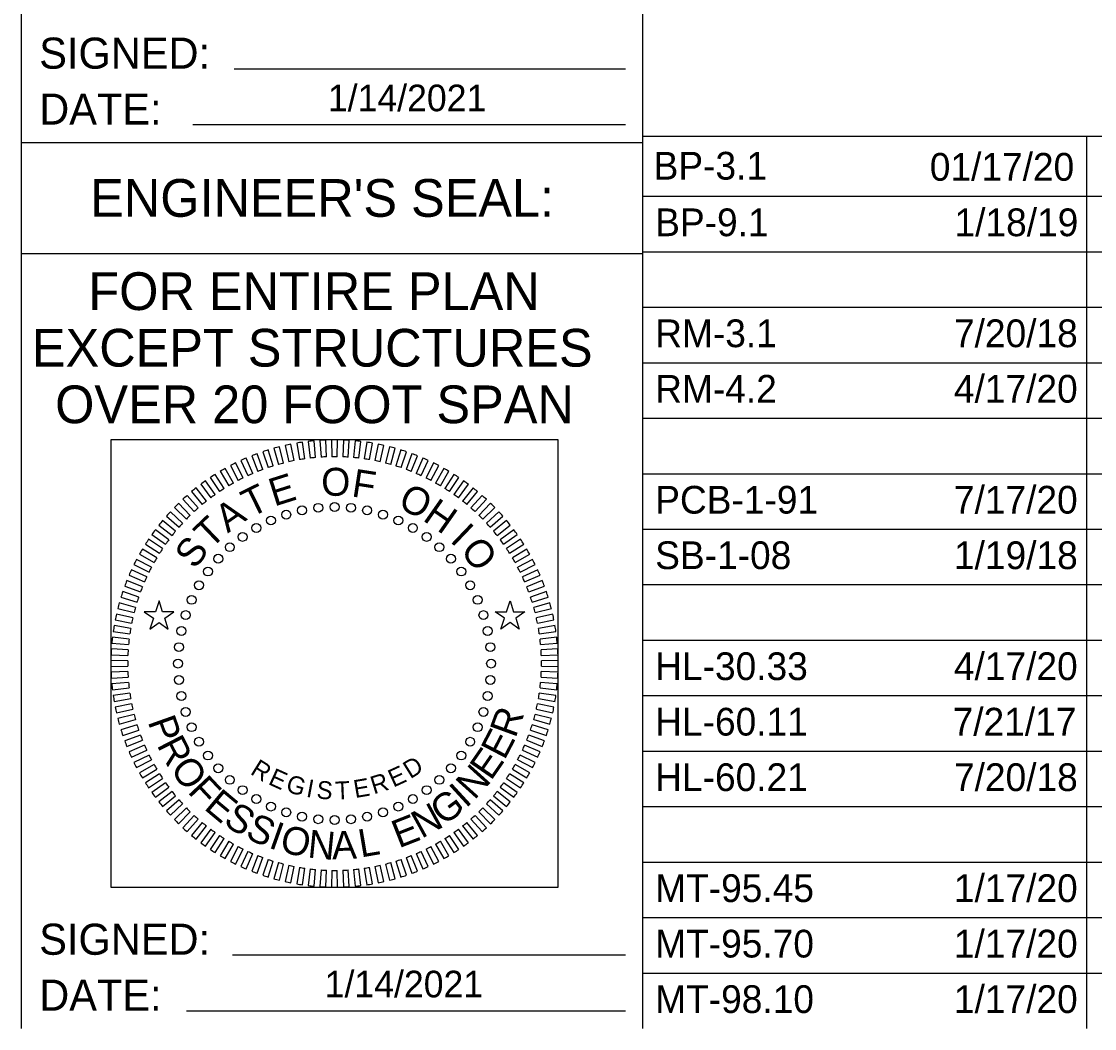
# Model space of a CAD drawing. Extents: x 2080852 to 2433556, y 1080825 to 1306626.
# Drawn here: x 2166916 to 2217967, y 1086105 to 1134021 of the extents above; entities that cross this region are included whole.
import ezdxf

# ---------------------------------------------------------------- set-up
doc = ezdxf.new("R2010")
doc.units = 0
for name, color, linetype in [('Default', 7, 'Continuous'), ('PM_P_Lane_Line', 7, 'Continuous'), ('SC_Scratch1', 7, 'Continuous')]:
    doc.layers.add(name, color=color, linetype=linetype)

msp = doc.modelspace()

# ---------------------------------------------------------------- linework, layer by layer
at = {"layer": 'PM_P_Lane_Line'}
for p, q in [((2166916, 1086105), (2166916, 1167965)), ((2196484, 1086105), (2196484, 1167965)), ((2177035, 1131774), (2195653, 1131774)), ((2175069, 1129114), (2195653, 1129114)), ((2166916, 1128264), (2196484, 1128264)), ((2196484, 1128566), (2338516, 1128566)), ((2217604, 1086105), (2217604, 1128566)), ((2196484, 1125705), (2338516, 1125705)), ((2166916, 1122984), (2196484, 1122984)), ((2196484, 1123065), (2338516, 1123065)), ((2196484, 1120425), (2338516, 1120425)), ((2196484, 1117785), (2338516, 1117785)), ((2196484, 1115145), (2338516, 1115145)), ((2180010, 1113959), (2180146, 1113173)), ((2180400, 1113213), (2180286, 1114003)), ((2180562, 1114039), (2180656, 1113246)), ((2180912, 1113273), (2180839, 1114068)), ((2181116, 1114090), (2181169, 1113294)), ((2181426, 1113307), (2181395, 1114104)), ((2181673, 1114112), (2181684, 1113314)), ((2181941, 1113314), (2181952, 1114112)), ((2182230, 1114104), (2182199, 1113307)), ((2182456, 1113294), (2182508, 1114090)), ((2182786, 1114068), (2182713, 1113273)), ((2182969, 1113246), (2183063, 1114039)), ((2183339, 1114003), (2183225, 1113213)), ((2183479, 1113173), (2183614, 1113959)), ((2178406, 1112706), (2178130, 1113455)), ((2178392, 1113548), (2178649, 1112792)), ((2178894, 1112872), (2178657, 1113634)), ((2178924, 1113713), (2179141, 1112945)), ((2179390, 1113012), (2179193, 1113785)), ((2179464, 1113850), (2179640, 1113072)), ((2179892, 1113126), (2179737, 1113908)), ((2183888, 1113908), (2183732, 1113126)), ((2183985, 1113072), (2184161, 1113850)), ((2184431, 1113785), (2184235, 1113012)), ((2184484, 1112945), (2184701, 1113713)), ((2184968, 1113634), (2184731, 1112872)), ((2184976, 1112792), (2185233, 1113548)), ((2185495, 1113455), (2185219, 1112706)), ((2177459, 1112300), (2177106, 1113015)), ((2177358, 1113135), (2177692, 1112411)), ((2177927, 1112515), (2177612, 1113249)), ((2177870, 1113355), (2178165, 1112614)), ((2185459, 1112614), (2185755, 1113355)), ((2186013, 1113249), (2185698, 1112515)), ((2185933, 1112411), (2186267, 1113135)), ((2186518, 1113015), (2186165, 1112300)), ((2176560, 1111796), (2176135, 1112471)), ((2176372, 1112617), (2176780, 1111931)), ((2177003, 1112060), (2176613, 1112756)), ((2176858, 1112889), (2177230, 1112183)), ((2186395, 1112183), (2186767, 1112889)), ((2187011, 1112756), (2186621, 1112060)), ((2186845, 1111931), (2187253, 1112617)), ((2187490, 1112471), (2187064, 1111796)), ((2196484, 1112505), (2338516, 1112505)), ((2175446, 1111998), (2175924, 1111359)), ((2176132, 1111510), (2175671, 1112162)), ((2175901, 1112319), (2176344, 1111656)), ((2187280, 1111656), (2187724, 1112319)), ((2187953, 1112162), (2187493, 1111510)), ((2187701, 1111359), (2188179, 1111998)), ((2175323, 1110872), (2174797, 1111472)), ((2175009, 1111653), (2175519, 1111040)), ((2175719, 1111202), (2175225, 1111828)), ((2188400, 1111828), (2187906, 1111202)), ((2188106, 1111040), (2188616, 1111653)), ((2188828, 1111472), (2188302, 1110872)), ((2174191, 1110897), (2174762, 1110340)), ((2174945, 1110522), (2174388, 1111094)), ((2174590, 1111286), (2175131, 1110700)), ((2188493, 1110700), (2189035, 1111286)), ((2189237, 1111094), (2188680, 1110522)), ((2188862, 1110340), (2189434, 1110897)), ((2173813, 1110488), (2174413, 1109962)), ((2174585, 1110153), (2173999, 1110695)), ((2189626, 1110695), (2189040, 1110153)), ((2189212, 1109962), (2189812, 1110488)), ((2173456, 1110060), (2174083, 1109566)), ((2174245, 1109766), (2173632, 1110276)), ((2189993, 1110276), (2189379, 1109766)), ((2189542, 1109566), (2190168, 1110060)), ((2196484, 1109865), (2338516, 1109865)), ((2173629, 1108941), (2172965, 1109384)), ((2173123, 1109613), (2173775, 1109153)), ((2173926, 1109361), (2173287, 1109839)), ((2190338, 1109839), (2189698, 1109361)), ((2189850, 1109153), (2190502, 1109613)), ((2190659, 1109384), (2189996, 1108941)), ((2173354, 1108505), (2172668, 1108913)), ((2172814, 1109150), (2173489, 1108724)), ((2190136, 1108724), (2190811, 1109150)), ((2190957, 1108913), (2190271, 1108505)), ((2173102, 1108055), (2172396, 1108427)), ((2172529, 1108672), (2173225, 1108282)), ((2190400, 1108282), (2191096, 1108672)), ((2191229, 1108427), (2190523, 1108055)), ((2172874, 1107593), (2172150, 1107927)), ((2172269, 1108179), (2172985, 1107826)), ((2190640, 1107826), (2191355, 1108179)), ((2191475, 1107927), (2190750, 1107593)), ((2172671, 1107120), (2171930, 1107415)), ((2172036, 1107673), (2172769, 1107358)), ((2190855, 1107358), (2191588, 1107673)), ((2191695, 1107415), (2190954, 1107120)), ((2172493, 1106636), (2171737, 1106893)), ((2171830, 1107155), (2172579, 1106879)), ((2191046, 1106879), (2191795, 1107155)), ((2191888, 1106893), (2191132, 1106636)), ((2196484, 1107225), (2338516, 1107225)), ((2172340, 1106144), (2171572, 1106361)), ((2171651, 1106628), (2172413, 1106391)), ((2191212, 1106391), (2191974, 1106628)), ((2192053, 1106361), (2191285, 1106144)), ((2172213, 1105645), (2171435, 1105821)), ((2171500, 1106092), (2172273, 1105895)), ((2191352, 1105895), (2192125, 1106092)), ((2192190, 1105821), (2191412, 1105645)), ((2172112, 1105139), (2171326, 1105274)), ((2171377, 1105548), (2172159, 1105393)), ((2191465, 1105393), (2192248, 1105548)), ((2192299, 1105274), (2191512, 1105139)), ((2171282, 1104999), (2172072, 1104885)), ((2191553, 1104885), (2192342, 1104999)), ((2171217, 1104446), (2172011, 1104373)), ((2172038, 1104629), (2171246, 1104723)), ((2192379, 1104723), (2191586, 1104629)), ((2191613, 1104373), (2192408, 1104446)), ((2196484, 1104585), (2338516, 1104585)), ((2171180, 1103890), (2171978, 1103859)), ((2171991, 1104116), (2171195, 1104168)), ((2192430, 1104168), (2191633, 1104116)), ((2191647, 1103859), (2192444, 1103890)), ((2171971, 1103601), (2171173, 1103612)), ((2171173, 1103333), (2171971, 1103344)), ((2192452, 1103612), (2191654, 1103601)), ((2191654, 1103344), (2192452, 1103333)), ((2171978, 1103086), (2171180, 1103055)), ((2171195, 1102777), (2171991, 1102829)), ((2191633, 1102829), (2192430, 1102777)), ((2192444, 1103055), (2191647, 1103086)), ((2172011, 1102572), (2171217, 1102499)), ((2171246, 1102222), (2172038, 1102316)), ((2191586, 1102316), (2192379, 1102222)), ((2192408, 1102499), (2191613, 1102572)), ((2172072, 1102060), (2171282, 1101946)), ((2171326, 1101671), (2172112, 1101806)), ((2191512, 1101806), (2192299, 1101671)), ((2192342, 1101946), (2191553, 1102060)), ((2196484, 1101945), (2338516, 1101945)), ((2172159, 1101552), (2171377, 1101397)), ((2171435, 1101124), (2172213, 1101300)), ((2191412, 1101300), (2192190, 1101124)), ((2192248, 1101397), (2191465, 1101552)), ((2172273, 1101050), (2171500, 1100853)), ((2171572, 1100584), (2172340, 1100801)), ((2191285, 1100801), (2192053, 1100584)), ((2192125, 1100853), (2191352, 1101050)), ((2172413, 1100554), (2171651, 1100317)), ((2171737, 1100052), (2172493, 1100309)), ((2191132, 1100309), (2191888, 1100052)), ((2191974, 1100317), (2191212, 1100554)), ((2172579, 1100066), (2171830, 1099790)), ((2171930, 1099530), (2172671, 1099825)), ((2190954, 1099825), (2191695, 1099530)), ((2191795, 1099790), (2191046, 1100066)), ((2172769, 1099587), (2172036, 1099272)), ((2172150, 1099018), (2172874, 1099352)), ((2190750, 1099352), (2191475, 1099018)), ((2191588, 1099272), (2190855, 1099587)), ((2196484, 1099305), (2338516, 1099305)), ((2172985, 1099119), (2172269, 1098766)), ((2172396, 1098518), (2173102, 1098890)), ((2173225, 1098663), (2172529, 1098273)), ((2191096, 1098273), (2190400, 1098663)), ((2190523, 1098890), (2191229, 1098518)), ((2191355, 1098766), (2190640, 1099119)), ((2172668, 1098032), (2173354, 1098440)), ((2173489, 1098221), (2172814, 1097795)), ((2190811, 1097795), (2190136, 1098221)), ((2190271, 1098440), (2190957, 1098032)), ((2172965, 1097561), (2173629, 1098004)), ((2173775, 1097792), (2173123, 1097332)), ((2190502, 1097332), (2189850, 1097792)), ((2189996, 1098004), (2190659, 1097561)), ((2173287, 1097106), (2173926, 1097584)), ((2174083, 1097379), (2173456, 1096885)), ((2173632, 1096669), (2174245, 1097179)), ((2189379, 1097179), (2189993, 1096669)), ((2190168, 1096885), (2189542, 1097379)), ((2189698, 1097584), (2190338, 1097106)), ((2174413, 1096983), (2173813, 1096457)), ((2173999, 1096250), (2174585, 1096792)), ((2174762, 1096605), (2174191, 1096048)), ((2189434, 1096048), (2188862, 1096605)), ((2189040, 1096792), (2189626, 1096250)), ((2189812, 1096457), (2189212, 1096983)), ((2196484, 1096665), (2338516, 1096665)), ((2174388, 1095851), (2174945, 1096423)), ((2175131, 1096245), (2174590, 1095659)), ((2174797, 1095473), (2175323, 1096073)), ((2188302, 1096073), (2188828, 1095473)), ((2189035, 1095659), (2188493, 1096245)), ((2188680, 1096423), (2189237, 1095851)), ((2175519, 1095905), (2175009, 1095292)), ((2175225, 1095117), (2175719, 1095743)), ((2175924, 1095586), (2175446, 1094947)), ((2188179, 1094947), (2187701, 1095586)), ((2187906, 1095743), (2188400, 1095117)), ((2188616, 1095292), (2188106, 1095905)), ((2175671, 1094783), (2176132, 1095435)), ((2176344, 1095289), (2175901, 1094625)), ((2176135, 1094474), (2176560, 1095149)), ((2187064, 1095149), (2187490, 1094474)), ((2187724, 1094625), (2187280, 1095289)), ((2187493, 1095435), (2187953, 1094783)), ((2176780, 1095014), (2176372, 1094328)), ((2176613, 1094189), (2177003, 1094885)), ((2177230, 1094762), (2176858, 1094056)), ((2177106, 1093930), (2177459, 1094645)), ((2177692, 1094534), (2177358, 1093810)), ((2186267, 1093810), (2185933, 1094534)), ((2186165, 1094645), (2186518, 1093930)), ((2186767, 1094056), (2186395, 1094762)), ((2186621, 1094885), (2187011, 1094189)), ((2187253, 1094328), (2186845, 1095014)), ((2177612, 1093696), (2177927, 1094430)), ((2178165, 1094331), (2177870, 1093590)), ((2178130, 1093490), (2178406, 1094239)), ((2178649, 1094153), (2178392, 1093397)), ((2178657, 1093311), (2178894, 1094073)), ((2184731, 1094073), (2184968, 1093311)), ((2185233, 1093397), (2184976, 1094153)), ((2185219, 1094239), (2185495, 1093490)), ((2185755, 1093590), (2185459, 1094331)), ((2185698, 1094430), (2186013, 1093696)), ((2196484, 1094025), (2338516, 1094025)), ((2179141, 1094000), (2178924, 1093232)), ((2179193, 1093160), (2179390, 1093933)), ((2179640, 1093873), (2179464, 1093095)), ((2179737, 1093037), (2179892, 1093819)), ((2180146, 1093772), (2180010, 1092986)), ((2180286, 1092942), (2180400, 1093732)), ((2180656, 1093699), (2180562, 1092906)), ((2180839, 1092877), (2180912, 1093672)), ((2181169, 1093651), (2181116, 1092855)), ((2181395, 1092840), (2181426, 1093638)), ((2181684, 1093631), (2181673, 1092833)), ((2181952, 1092833), (2181941, 1093631)), ((2182199, 1093638), (2182230, 1092840)), ((2182508, 1092855), (2182456, 1093651)), ((2182713, 1093672), (2182786, 1092877)), ((2183063, 1092906), (2182969, 1093699)), ((2183225, 1093732), (2183339, 1092942)), ((2183614, 1092986), (2183479, 1093772)), ((2183732, 1093819), (2183888, 1093037)), ((2184161, 1093095), (2183985, 1093873)), ((2184235, 1093933), (2184431, 1093160)), ((2184701, 1093232), (2184484, 1094000)), ((2196484, 1091385), (2338516, 1091385)), ((2176960, 1089615), (2195653, 1089615)), ((2196484, 1088745), (2338516, 1088745)), ((2174767, 1086955), (2195653, 1086955))]:
    msp.add_line(p, q, dxfattribs=at)
for points in [[(2173897, 1105112), (2173731, 1105623), (2174165, 1105939), (2173628, 1105939), (2173462, 1106450), (2173296, 1105939), (2172758, 1105939), (2173193, 1105623), (2173027, 1105112), (2173462, 1105427), (2173897, 1105112)], [(2189728, 1105112), (2189894, 1105623), (2189459, 1105939), (2189997, 1105939), (2190163, 1106450), (2190329, 1105939), (2190867, 1105939), (2190432, 1105623), (2190598, 1105112), (2190163, 1105427), (2189728, 1105112)]]:
    msp.add_lwpolyline(points, dxfattribs=at)
for centre in [(2180264, 1110758), (2181034, 1110880), (2181812, 1110921), (2182591, 1110880), (2183361, 1110758), (2178783, 1110277), (2179511, 1110556), (2184114, 1110556), (2184842, 1110277), (2178088, 1109923), (2185536, 1109923), (2177434, 1109498), (2186190, 1109498), (2176829, 1109008), (2186796, 1109008), (2176277, 1108456), (2187347, 1108456), (2175787, 1107850), (2187838, 1107850), (2175362, 1107197), (2188263, 1107197), (2175008, 1106502), (2188617, 1106502), (2174729, 1105774), (2188896, 1105774), (2174527, 1105021), (2189098, 1105021), (2174405, 1104251), (2189220, 1104251), (2174364, 1103472), (2189260, 1103472), (2174405, 1102694), (2189220, 1102694), (2174527, 1101924), (2189098, 1101924), (2174729, 1101171), (2188896, 1101171), (2175008, 1100443), (2188617, 1100443), (2175362, 1099748), (2188263, 1099748), (2175787, 1099095), (2187838, 1099095), (2176277, 1098489), (2187347, 1098489), (2176829, 1097937), (2186796, 1097937), (2177434, 1097447), (2186190, 1097447), (2178088, 1097022), (2185536, 1097022), (2178783, 1096668), (2179511, 1096389), (2184114, 1096389), (2184842, 1096668), (2180264, 1096187), (2181034, 1096065), (2181812, 1096024), (2182591, 1096065), (2183361, 1096187)]:
    msp.add_circle(centre, 213, dxfattribs=at)
for radius, start, end in [(10640, 98.25, 99.75), (10640, 95.25, 96.75), (10640, 92.25, 93.75), (10640, 89.25, 90.75), (10640, 86.25, 87.75), (10640, 83.25, 84.75), (10640, 80.25, 81.75), (10640, 110.25, 111.75), (10640, 107.25, 108.75), (10640, 104.25, 105.75), (10640, 101.25, 102.75), (10640, 77.25, 78.75), (10640, 74.25, 75.75), (10640, 71.25, 72.75), (10640, 68.25, 69.75), (10640, 116.25, 117.75), (10640, 113.25, 114.75), (9842, 104.25, 105.75), (9842, 101.25, 102.75), (9842, 98.25, 99.75), (9842, 95.25, 96.75), (9842, 92.25, 93.75), (9842, 89.25, 90.75), (9842, 86.25, 87.75), (9842, 83.25, 84.75), (9842, 80.25, 81.75), (9842, 77.25, 78.75), (9842, 74.25, 75.75), (10640, 65.25, 66.75), (10640, 62.25, 63.75), (10640, 122.25, 123.75), (10640, 119.25, 120.75), (9842, 113.25, 114.75), (9842, 110.25, 111.75), (9842, 107.25, 108.75), (9842, 71.25, 72.75), (9842, 68.25, 69.75), (9842, 65.25, 66.75), (10640, 59.25, 60.75), (10640, 56.25, 57.75), (10640, 125.25, 126.75), (9842, 119.25, 120.75), (9842, 116.25, 117.75), (9842, 62.25, 63.75), (9842, 59.25, 60.75), (10640, 53.25, 54.75), (10640, 131.25, 132.75), (10640, 128.25, 129.75), (9842, 125.25, 126.75), (9842, 122.25, 123.75), (9842, 56.25, 57.75), (9842, 53.25, 54.75), (10640, 50.25, 51.75), (10640, 47.25, 48.75), (10640, 134.25, 135.75), (9842, 131.25, 132.75), (9842, 128.25, 129.75), (9842, 50.25, 51.75), (9842, 47.25, 48.75), (10640, 44.25, 45.75), (10640, 137.25, 138.75), (9842, 134.25, 135.75), (9842, 44.25, 45.75), (10640, 41.25, 42.75), (10640, 140.25, 141.75), (9842, 137.25, 138.75), (9842, 41.25, 42.75), (10640, 38.25, 39.75), (10640, 146.25, 147.75), (10640, 143.25, 144.75), (9842, 143.25, 144.75), (9842, 140.25, 141.75), (9842, 38.25, 39.75), (9842, 35.25, 36.75), (10640, 35.25, 36.75), (10640, 32.25, 33.75), (10640, 149.25, 150.75), (9842, 146.25, 147.75), (9842, 32.25, 33.75), (10640, 29.25, 30.75), (10640, 152.25, 153.75), (9842, 149.25, 150.75), (9842, 29.25, 30.75), (10640, 26.25, 27.75), (10640, 155.25, 156.75), (9842, 152.25, 153.75), (9842, 26.25, 27.75), (10640, 23.25, 24.75), (10640, 158.25, 159.75), (9842, 155.25, 156.75), (9842, 23.25, 24.75), (10640, 20.25, 21.75), (10640, 161.25, 162.75), (9842, 158.25, 159.75), (9842, 20.25, 21.75), (10640, 17.25, 18.75), (10640, 164.25, 165.75), (9842, 161.25, 162.75), (9842, 17.25, 18.75), (10640, 14.25, 15.75), (10640, 167.25, 168.75), (9842, 164.25, 165.75), (9842, 14.25, 15.75), (10640, 11.25, 12.75), (10640, 170.25, 171.75), (9842, 167.25, 168.75), (9842, 11.25, 12.75), (10640, 8.25, 9.75), (9842, 170.25, 171.75), (9842, 8.25, 9.75), (10640, 173.25, 174.75), (9842, 173.25, 174.75), (9842, 5.25, 6.75), (10640, 5.25, 6.75), (10640, 176.25, 177.75), (9842, 176.25, 177.75), (9842, 2.25, 3.75), (10640, 2.25, 3.75), (10640, 179.25, 180.75), (9842, 179.25, 180.75), (9842, 359.25, 0.75), (10640, 359.25, 0.75), (10640, 182.25, 183.75), (9842, 182.25, 183.75), (9842, 356.25, 357.75), (10640, 356.25, 357.75), (10640, 185.25, 186.75), (9842, 185.25, 186.75), (9842, 353.25, 354.75), (10640, 353.25, 354.75), (10640, 188.25, 189.75), (9842, 188.25, 189.75), (9842, 350.25, 351.75), (10640, 350.25, 351.75), (10640, 191.25, 192.75), (9842, 191.25, 192.75), (9842, 347.25, 348.75), (10640, 347.25, 348.75), (10640, 194.25, 195.75), (9842, 194.25, 195.75), (9842, 344.25, 345.75), (10640, 344.25, 345.75), (10640, 197.25, 198.75), (9842, 197.25, 198.75), (9842, 341.25, 342.75), (10640, 341.25, 342.75), (10640, 200.25, 201.75), (9842, 200.25, 201.75), (9842, 338.25, 339.75), (10640, 338.25, 339.75), (10640, 203.25, 204.75), (9842, 203.25, 204.75), (9842, 335.25, 336.75), (10640, 335.25, 336.75), (10640, 206.25, 207.75), (9842, 206.25, 207.75), (9842, 209.25, 210.75), (9842, 329.25, 330.75), (9842, 332.25, 333.75), (10640, 332.25, 333.75), (10640, 209.25, 210.75), (9842, 212.25, 213.75), (9842, 326.25, 327.75), (10640, 329.25, 330.75), (10640, 212.25, 213.75), (9842, 215.25, 216.75), (9842, 323.25, 324.75), (10640, 326.25, 327.75), (10640, 215.25, 216.75), (9842, 218.25, 219.75), (9842, 320.25, 321.75), (10640, 323.25, 324.75), (10640, 218.25, 219.75), (9842, 221.25, 222.75), (9842, 224.25, 225.75), (9842, 314.25, 315.75), (9842, 317.25, 318.75), (10640, 320.25, 321.75), (10640, 221.25, 222.75), (9842, 227.25, 228.75), (9842, 311.25, 312.75), (10640, 317.25, 318.75), (10640, 224.25, 225.75), (10640, 227.25, 228.75), (9842, 230.25, 231.75), (9842, 233.25, 234.75), (9842, 305.25, 306.75), (9842, 308.25, 309.75), (10640, 311.25, 312.75), (10640, 314.25, 315.75), (10640, 230.25, 231.75), (9842, 236.25, 237.75), (9842, 302.25, 303.75), (10640, 308.25, 309.75), (10640, 233.25, 234.75), (10640, 236.25, 237.75), (9842, 239.25, 240.75), (9842, 242.25, 243.75), (9842, 245.25, 246.75), (9842, 293.25, 294.75), (9842, 296.25, 297.75), (9842, 299.25, 300.75), (10640, 302.25, 303.75), (10640, 305.25, 306.75), (10640, 239.25, 240.75), (10640, 242.25, 243.75), (9842, 248.25, 249.75), (9842, 251.25, 252.75), (9842, 287.25, 288.75), (9842, 290.25, 291.75), (10640, 296.25, 297.75), (10640, 299.25, 300.75), (10640, 245.25, 246.75), (10640, 248.25, 249.75), (9842, 254.25, 255.75), (9842, 257.25, 258.75), (9842, 260.25, 261.75), (9842, 263.25, 264.75), (9842, 266.25, 267.75), (9842, 269.25, 270.75), (9842, 272.25, 273.75), (9842, 275.25, 276.75), (9842, 278.25, 279.75), (9842, 281.25, 282.75), (9842, 284.25, 285.75), (10640, 290.25, 291.75), (10640, 293.25, 294.75), (10640, 251.25, 252.75), (10640, 254.25, 255.75), (10640, 257.25, 258.75), (10640, 281.25, 282.75), (10640, 284.25, 285.75), (10640, 287.25, 288.75), (10640, 260.25, 261.75), (10640, 263.25, 264.75), (10640, 266.25, 267.75), (10640, 269.25, 270.75), (10640, 272.25, 273.75), (10640, 275.25, 276.75), (10640, 278.25, 279.75)]:
    msp.add_arc((2181812, 1103472), radius, start, end, dxfattribs=at)
at = {"layer": 'SC_Scratch1'}
msp.add_lwpolyline([(2192453, 1114113), (2171172, 1114113), (2171172, 1092832), (2192453, 1092832)], close=True, dxfattribs=at)

# ---------------------------------------------------------------- texts
at = {"layer": 'Default'}
msp.add_text("ENGINEER'S SEAL:", height=1795.2, dxfattribs=at).set_placement((2170185, 1124727))
at = {"layer": 'PM_P_Lane_Line'}
for s, height, p in [('SIGNED:', 1478.4, (2167761, 1131774)), ('1/14/2021', 1267.2, (2181493, 1129748)), ('DATE:', 1478.4, (2167761, 1129114)), ('BP-3.1', 1320, (2196990, 1126496)), ('01/17/20', 1320, (2210129, 1126444)), ('1/18/19', 1320, (2211307, 1123804)), ('BP-9.1', 1320, (2197065, 1123804)), ('FOR ENTIRE PLAN ', 1795.2, (2170098, 1120291)), ('RM-3.1', 1320, (2197065, 1118524)), ('7/20/18', 1320, (2211280, 1118524)), ('EXCEPT STRUCTURES ', 1795.2, (2167413, 1117599)), ('RM-4.2', 1320, (2197065, 1115884)), ('4/17/20', 1320, (2211277, 1115884)), ('OVER 20 FOOT SPAN', 1795.2, (2168518, 1114906)), ('PCB-1-91', 1320, (2197065, 1110604)), ('7/17/20', 1320, (2211277, 1110604)), ('1/19/18', 1320, (2211280, 1107964)), ('SB-1-08', 1320, (2197065, 1107964)), ('HL-30.33', 1320, (2197065, 1102684)), ('4/17/20', 1320, (2211277, 1102684)), ('HL-60.11', 1320, (2197065, 1100044)), ('7/21/17', 1320, (2211215, 1100044)), ('HL-60.21', 1320, (2197065, 1097404)), ('7/20/18', 1320, (2211280, 1097404)), ('1/17/20', 1320, (2211277, 1092124)), ('MT-95.45', 1320, (2197065, 1092124)), ('SIGNED:', 1478.4, (2167761, 1089615)), ('MT-95.70', 1320, (2197065, 1089484)), ('1/17/20', 1320, (2211277, 1089484)), ('1/14/2021', 1267.2, (2181342, 1087588)), ('DATE:', 1478.4, (2167761, 1086955)), ('MT-98.10', 1320, (2197065, 1086844)), ('1/17/20', 1320, (2211277, 1086844))]:
    msp.add_text(s, height=height, dxfattribs=at).set_placement(p)
for s, height, rotation, p in [('E', 1330, 17.4881, (2178941, 1110935)), ('O', 1330, 360, (2181177, 1111453)), ('F', 1330, 351.2559, (2182583, 1111428)), ('T', 1330, 26.2322, (2177813, 1110398)), ('O', 1330, 333.7678, (2184769, 1110912)), ('A', 1330, 34.9763, (2176728, 1109655)), ('H', 1330, 325.0237, (2185960, 1110310)), ('T', 1330, 43.7204, (2175916, 1108876)), ('I', 1330, 316.2796, (2187264, 1109301)), ('S', 1330, 52.4644, (2175163, 1107916)), ('O', 1330, 307.5356, (2187753, 1108839)), ('R', 1330, 70.0588, (2190415, 1099885)), ('P', 1330, 289.5814, (2172913, 1100710)), ('E', 1330, 62.4535, (2189895, 1098837)), ('R', 1330, 297.2357, (2173334, 1099601)), ('E', 1330, 55.2557, (2189251, 1097861)), ('O', 1330, 305.4844, (2173955, 1098456)), ('R', 851, 328.1824, (2177759, 1098240)), ('E', 851, 24.6051, (2184608, 1097563)), ('D', 851, 31.9496, (2185417, 1097962)), ('N', 1330, 47.9322, (2188461, 1096943)), ('F', 1330, 313.1051, (2174785, 1097356)), ('E', 851, 335.6609, (2178613, 1097746)), ('G', 851, 343.2553, (2179445, 1097397)), ('R', 851, 17.1266, (2183675, 1097243)), ('I', 851, 349.2987, (2180427, 1097139)), ('S', 851, 355.0096, (2180930, 1097055)), ('T', 851, 2.3896, (2181861, 1097001)), ('E', 851, 9.6483, (2182790, 1097068)), ('I', 1330, 42.4932, (2188053, 1096563)), ('E', 1330, 320.0821, (2175553, 1096571)), ('G', 1330, 36.6302, (2186997, 1095726)), ('S', 1330, 327.427, (2176466, 1095840)), ('N', 1330, 28.7584, (2185948, 1095122)), ('S', 1330, 334.919, (2177507, 1095208)), ('E', 1330, 21.4349, (2184868, 1094670)), ('I', 1330, 340.3806, (2178624, 1094725)), ('O', 1330, 346.3372, (2179150, 1094538)), ('N', 1330, 354.3042, (2180498, 1094247)), ('L', 1330, 9.6097, (2183060, 1094241)), ('A', 1330, 2.2066, (2181705, 1094151))]:
    msp.add_text(s, height=height, rotation=rotation, dxfattribs=at).set_placement(p)

doc.saveas('drawing.dxf')
